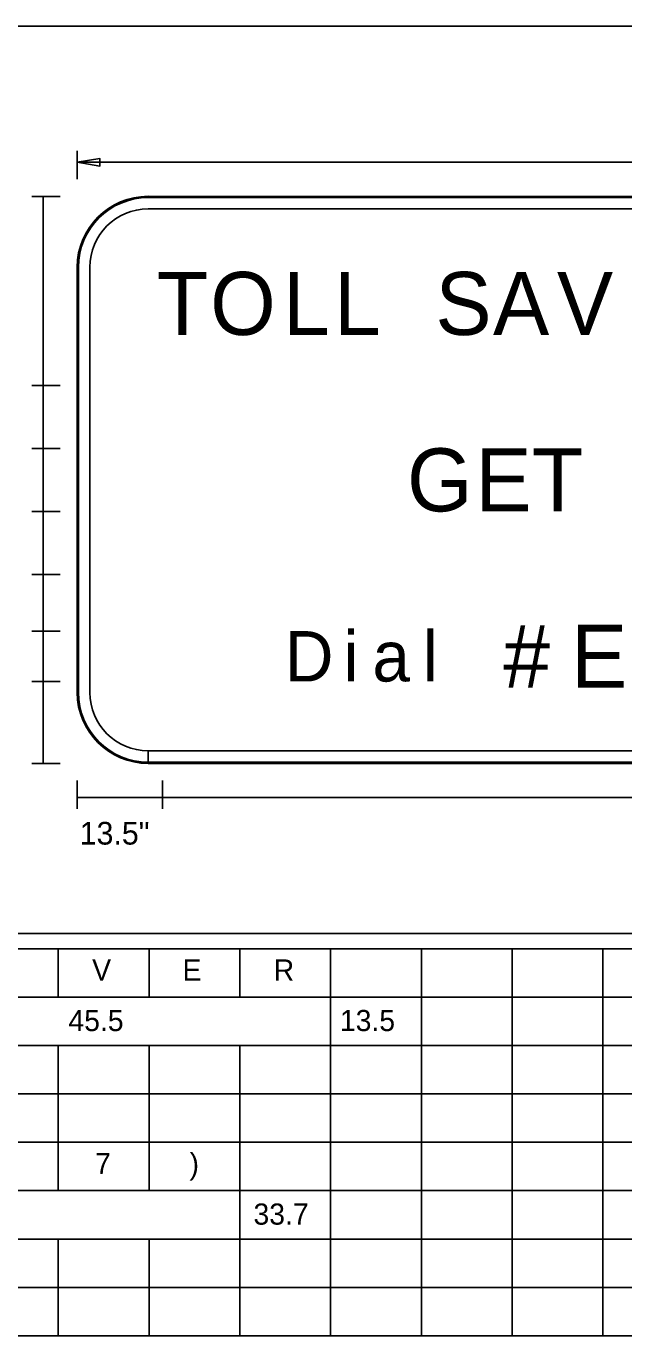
# Model space of a CAD drawing. Extents: x 10268312 to 10268471, y 2141099 to 2141204.
# Drawn here: x 10268380.92 to 10268400.67, y 2141160.23 to 2141203.53 of the extents above; entities that cross this region are included whole.
import ezdxf

# ---------------------------------------------------------------- set-up
doc = ezdxf.new("R2010")
doc.units = 0
for name, color, linetype in [('GSBWFill', 7, 'Continuous'), ('GSColorFill', 7, 'Continuous'), ('GSDims', 7, 'Continuous'), ('GSOutline', 7, 'Continuous'), ('SumBoxLines_dp', 7, 'Continuous'), ('SumBoxLinesMin_dp', 7, 'Continuous'), ('TextLabel', 7, 'Continuous')]:
    doc.layers.add(name, color=color, linetype=linetype)

msp = doc.modelspace()

# ---------------------------------------------------------------- linework, layer by layer
at = {"layer": 'GSBWFill'}
for p, q in [((10268427.762, 2141197.903), (10268384.949, 2141197.903)), ((10268384.949, 2141197.487), (10268427.762, 2141197.487)), ((10268382.605, 2141195.56), (10268382.605, 2141181.497)), ((10268383.022, 2141181.497), (10268383.022, 2141195.56)), ((10268384.949, 2141179.153), (10268384.949, 2141179.57)), ((10268427.762, 2141179.57), (10268384.953, 2141179.57)), ((10268384.953, 2141179.57), (10268384.953, 2141179.153)), ((10268384.953, 2141179.153), (10268427.762, 2141179.153))]:
    msp.add_line(p, q, dxfattribs=at)
for centre, radius, start, end in [((10268384.949, 2141195.56), 2.344, 90, 180), ((10268384.949, 2141195.56), 1.927, 90, 180), ((10268384.949, 2141181.497), 2.344, 180, 270), ((10268384.949, 2141181.497), 1.927, 180, 270)]:
    msp.add_arc(centre, radius, start, end, dxfattribs=at)
at = {"layer": 'GSColorFill'}
for p, q in [((10268427.762, 2141197.903), (10268384.949, 2141197.903)), ((10268427.762, 2141197.903), (10268384.949, 2141197.903)), ((10268427.762, 2141197.903), (10268384.949, 2141197.903)), ((10268384.949, 2141197.862), (10268427.762, 2141197.862)), ((10268384.949, 2141197.487), (10268427.762, 2141197.487)), ((10268382.605, 2141195.56), (10268382.605, 2141181.497)), ((10268382.605, 2141195.56), (10268382.605, 2141181.497)), ((10268382.605, 2141195.56), (10268382.605, 2141181.497)), ((10268382.647, 2141181.497), (10268382.647, 2141195.56)), ((10268383.022, 2141181.497), (10268383.022, 2141195.56)), ((10268384.949, 2141179.153), (10268384.949, 2141179.57)), ((10268427.762, 2141179.57), (10268384.953, 2141179.57)), ((10268384.953, 2141179.57), (10268384.953, 2141179.153)), ((10268384.949, 2141179.153), (10268384.949, 2141179.195)), ((10268427.762, 2141179.195), (10268384.949, 2141179.195)), ((10268384.949, 2141179.195), (10268384.949, 2141179.153)), ((10268384.949, 2141179.153), (10268427.762, 2141179.153)), ((10268384.949, 2141179.153), (10268427.762, 2141179.153)), ((10268384.953, 2141179.153), (10268427.762, 2141179.153))]:
    msp.add_line(p, q, dxfattribs=at)
for centre, radius, start, end in [((10268384.949, 2141195.56), 2.344, 90, 180), ((10268384.949, 2141195.56), 2.344, 90, 180), ((10268384.949, 2141195.56), 2.344, 90, 180), ((10268384.949, 2141195.56), 2.302, 90, 180), ((10268384.949, 2141195.56), 1.927, 90, 180), ((10268384.949, 2141181.497), 2.344, 180, 270), ((10268384.949, 2141181.497), 2.344, 180, 270), ((10268384.949, 2141181.497), 2.344, 180, 270), ((10268384.949, 2141181.497), 2.302, 180, 270), ((10268384.949, 2141181.497), 1.927, 180, 270)]:
    msp.add_arc(centre, radius, start, end, dxfattribs=at)
at = {"layer": 'GSDims'}
for p, q in [((10268382.605, 2141198.466), (10268382.605, 2141199.403)), ((10268382.605, 2141199.028), (10268430.105, 2141199.028)), ((10268382.043, 2141197.903), (10268381.105, 2141197.903)), ((10268381.48, 2141197.903), (10268381.48, 2141191.653)), ((10268382.043, 2141191.653), (10268381.105, 2141191.653)), ((10268381.48, 2141191.653), (10268381.48, 2141189.57)), ((10268382.043, 2141189.57), (10268381.105, 2141189.57)), ((10268381.48, 2141189.57), (10268381.48, 2141187.487)), ((10268382.043, 2141187.487), (10268381.105, 2141187.487)), ((10268381.48, 2141183.528), (10268381.48, 2141187.487)), ((10268382.043, 2141185.403), (10268381.105, 2141185.403)), ((10268382.043, 2141183.528), (10268381.105, 2141183.528)), ((10268382.043, 2141183.528), (10268381.105, 2141183.528)), ((10268381.48, 2141183.528), (10268381.48, 2141181.862)), ((10268382.043, 2141181.862), (10268381.105, 2141181.862)), ((10268382.043, 2141181.862), (10268381.105, 2141181.862)), ((10268381.48, 2141179.153), (10268381.48, 2141181.862)), ((10268382.043, 2141179.153), (10268381.105, 2141179.153)), ((10268382.605, 2141178.591), (10268382.605, 2141177.653)), ((10268385.418, 2141178.591), (10268385.418, 2141177.653)), ((10268385.418, 2141178.591), (10268385.418, 2141177.653)), ((10268382.605, 2141178.028), (10268385.418, 2141178.028)), ((10268385.418, 2141178.028), (10268427.293, 2141178.028))]:
    msp.add_line(p, q, dxfattribs=at)
msp.add_lwpolyline([(10268382.605, 2141199.028), (10268383.355, 2141198.903), (10268383.355, 2141199.153)], close=True, dxfattribs=at)
at = {"layer": 'GSOutline'}
for p, q in [((10268427.762, 2141197.903), (10268384.949, 2141197.903)), ((10268427.762, 2141197.487), (10268384.949, 2141197.487)), ((10268382.605, 2141195.56), (10268382.605, 2141181.497)), ((10268383.022, 2141195.56), (10268383.022, 2141181.497)), ((10268384.949, 2141179.57), (10268427.762, 2141179.57)), ((10268384.949, 2141179.153), (10268427.762, 2141179.153))]:
    msp.add_line(p, q, dxfattribs=at)
for centre, radius, start, end in [((10268384.949, 2141195.56), 2.344, 90, 180), ((10268384.949, 2141195.56), 1.927, 90, 180), ((10268384.949, 2141181.497), 2.344, 180, 270), ((10268384.949, 2141181.497), 1.927, 180, 270)]:
    msp.add_arc(centre, radius, start, end, dxfattribs=at)
at = {"layer": 'SumBoxLines_dp'}
for p, q in [((10268341.73, 2141203.528), (10268470.98, 2141203.528)), ((10268341.73, 2141173.528), (10268470.98, 2141173.528)), ((10268318.48, 2141173.028), (10268470.98, 2141173.028)), ((10268381.98, 2141173.028), (10268381.98, 2141171.428)), ((10268384.98, 2141173.028), (10268384.98, 2141171.428)), ((10268387.98, 2141173.028), (10268387.98, 2141171.428)), ((10268390.98, 2141173.028), (10268390.98, 2141170.642)), ((10268393.98, 2141173.028), (10268393.98, 2141160.228)), ((10268396.98, 2141173.028), (10268396.98, 2141163.428)), ((10268399.98, 2141173.028), (10268399.98, 2141160.228)), ((10268390.98, 2141170.642), (10268390.98, 2141160.228)), ((10268318.48, 2141169.828), (10268470.98, 2141169.828)), ((10268381.98, 2141169.828), (10268381.98, 2141165.028)), ((10268384.98, 2141169.828), (10268384.98, 2141165.028)), ((10268387.98, 2141169.828), (10268387.98, 2141160.228)), ((10268318.48, 2141166.628), (10268470.98, 2141166.628)), ((10268318.48, 2141163.428), (10268470.98, 2141163.428)), ((10268381.98, 2141163.428), (10268381.98, 2141160.228)), ((10268384.98, 2141163.428), (10268384.98, 2141160.228)), ((10268396.98, 2141163.428), (10268396.98, 2141160.228)), ((10268318.48, 2141160.228), (10268470.98, 2141160.228))]:
    msp.add_line(p, q, dxfattribs=at)
at = {"layer": 'SumBoxLinesMin_dp'}
for p, q in [((10268318.48, 2141171.428), (10268470.98, 2141171.428)), ((10268318.48, 2141168.228), (10268470.98, 2141168.228)), ((10268318.48, 2141165.028), (10268470.98, 2141165.028)), ((10268318.48, 2141161.828), (10268470.98, 2141161.828))]:
    msp.add_line(p, q, dxfattribs=at)

# ---------------------------------------------------------------- texts
at = {"layer": 'GSBWFill'}
for s, height, p in [('T', 2.083, (10268385.23, 2141193.32)), ('O', 2.083, (10268386.999, 2141193.32)), ('L', 2.083, (10268389.403, 2141193.32)), ('L', 2.083, (10268391.089, 2141193.32)), ('S', 2.083, (10268394.441, 2141193.32)), ('A', 2.083, (10268396.345, 2141193.32)), ('V', 2.083, (10268398.457, 2141193.32)), ('G', 2.083, (10268393.503, 2141187.487)), ('E', 2.083, (10268395.762, 2141187.487)), ('T', 2.083, (10268397.631, 2141187.487)), ('#', 2.083, (10268396.687, 2141181.653)), ('E', 2.083, (10268398.922, 2141181.653)), ('D', 1.667, (10268389.463, 2141181.862)), ('i', 1.667, (10268391.406, 2141181.862)), ('l', 1.667, (10268394.03, 2141181.862)), ('a', 1.667, (10268392.359, 2141181.862))]:
    msp.add_text(s, height=height, dxfattribs=at).set_placement(p)
at = {"layer": 'GSColorFill'}
for s, height, p in [('T', 2.083, (10268385.23, 2141193.32)), ('O', 2.083, (10268386.999, 2141193.32)), ('L', 2.083, (10268389.403, 2141193.32)), ('L', 2.083, (10268391.089, 2141193.32)), ('S', 2.083, (10268394.441, 2141193.32)), ('A', 2.083, (10268396.345, 2141193.32)), ('V', 2.083, (10268398.457, 2141193.32)), ('G', 2.083, (10268393.503, 2141187.487)), ('E', 2.083, (10268395.762, 2141187.487)), ('T', 2.083, (10268397.631, 2141187.487)), ('#', 2.083, (10268396.687, 2141181.653)), ('E', 2.083, (10268398.922, 2141181.653)), ('D', 1.667, (10268389.463, 2141181.862)), ('i', 1.667, (10268391.406, 2141181.862)), ('l', 1.667, (10268394.03, 2141181.862)), ('a', 1.667, (10268392.359, 2141181.862))]:
    msp.add_text(s, height=height, dxfattribs=at).set_placement(p)
at = {"layer": 'GSDims'}
msp.add_text('13.5"', height=0.75, dxfattribs=at).set_placement((10268382.686, 2141176.47))
at = {"layer": 'TextLabel'}
for s, p in [('V', (10268383.099, 2141171.973)), ('E', (10268386.085, 2141171.973)), ('R', (10268389.097, 2141171.973)), ('45.5', (10268382.315, 2141170.303)), ('13.5', (10268391.286, 2141170.303)), ('7', (10268383.197, 2141165.573)), (')', (10268386.317, 2141165.573)), ('33.7', (10268388.43, 2141163.903))]:
    msp.add_text(s, height=0.7, dxfattribs=at).set_placement(p)

doc.saveas('drawing.dxf')
